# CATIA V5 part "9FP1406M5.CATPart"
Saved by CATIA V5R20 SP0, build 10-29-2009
Part number: 9FP1406M5
Revision: ANY
Definition: UNKNOWN
Nomenclature: 9FP1406M5
Source: Unknown
Bounding box of the stored display mesh (mm): x -6.727 to 6.727, y 0 to 6, z -6.9 to 6.9
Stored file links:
  C:\Users\Utente\Desktop\IO LAVORO\3D X SITO CF\CUMSA\3D files PW\pw081225\pw081225_ejection\9FP1406M5.CATPart
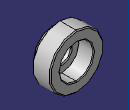
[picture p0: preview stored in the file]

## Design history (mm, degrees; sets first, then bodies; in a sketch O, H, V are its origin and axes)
Body1 "Chaflán1" (main body)
  Solid1: solid without history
